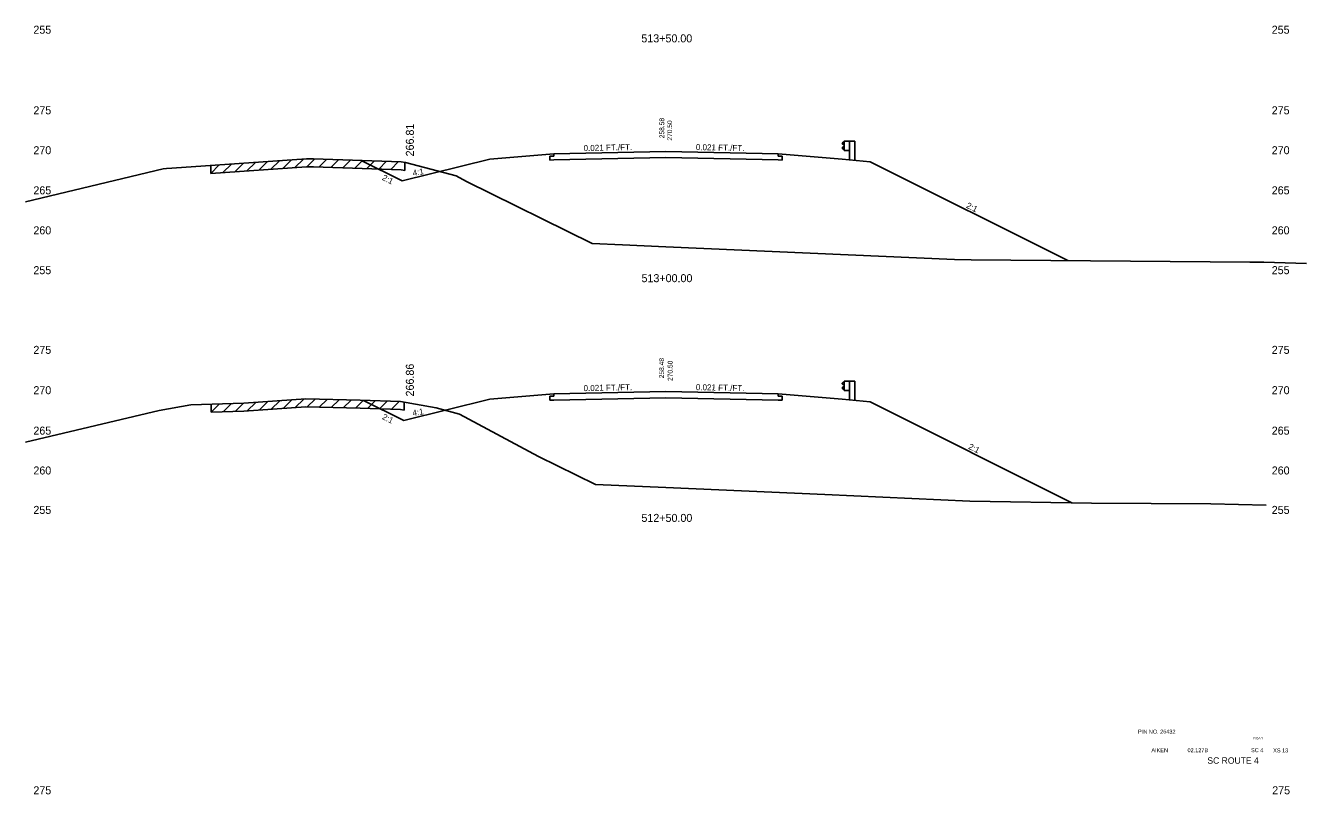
# Model space of a CAD drawing. Extents: x 883 to 1160, y 1002 to 4323.
# Drawn here: x 1000 to 1160, y 2475.1 to 2571.2 of the extents above; entities that cross this region are included whole.
import ezdxf

# ---------------------------------------------------------------- set-up
doc = ezdxf.new("R2010")
doc.units = 0
for name, color, linetype in [('Level 1', 7, 'Continuous'), ('Level 10', 7, 'Continuous'), ('Level 11', 7, 'Continuous'), ('Level 12', 7, 'Continuous'), ('Level 24', 7, 'Continuous'), ('Level 3', 7, 'Continuous'), ('Level 32', 7, 'Continuous'), ('Level 33', 7, 'Continuous'), ('Level 59', 7, 'Continuous'), ('Level 6', 7, 'Continuous'), ('Level 60', 7, 'Continuous'), ('Level 61', 7, 'Continuous'), ('Level 7', 7, 'Continuous')]:
    doc.layers.add(name, color=color, linetype=linetype)

msp = doc.modelspace()

# ---------------------------------------------------------------- linework, layer by layer
at = {"layer": 'Level 11'}
for p, q in [((1066, 2555.21), (1066, 2554.91)), ((1094, 2554.91), (1094, 2555.21)), ((1066, 2554.91), (1065.5, 2554.9)), ((1065.5, 2554.9), (1065.5, 2554.42)), ((1065.5, 2554.42), (1066, 2554.43)), ((1094.5, 2554.9), (1094, 2554.91)), ((1094, 2554.43), (1094.5, 2554.42)), ((1094.5, 2554.42), (1094.5, 2554.9)), ((1066, 2524.91), (1065.5, 2524.9)), ((1065.5, 2524.9), (1065.5, 2524.42)), ((1066, 2525.21), (1066, 2524.91)), ((1094, 2524.91), (1094, 2525.21)), ((1094.5, 2524.9), (1094, 2524.91)), ((1094.5, 2524.42), (1094.5, 2524.9)), ((1065.5, 2524.42), (1066, 2524.43)), ((1094, 2524.43), (1094.5, 2524.42))]:
    msp.add_line(p, q, dxfattribs=at)
at = {"layer": 'Level 12'}
for p, q in [((1080, 2554.72), (1066, 2554.43)), ((1094, 2554.43), (1080, 2554.72)), ((1080, 2524.72), (1066, 2524.43)), ((1094, 2524.43), (1080, 2524.72))]:
    msp.add_line(p, q, dxfattribs=at)
at = {"layer": 'Level 24'}
for p, q in [((1102.27, 2556.72), (1102, 2556.52)), ((1102, 2556.52), (1102, 2556.47)), ((1102, 2556.47), (1102.27, 2556.27)), ((1102, 2555.95), (1102.27, 2556.15)), ((1102, 2555.9), (1102, 2555.95)), ((1102.27, 2555.7), (1102, 2555.9)), ((1102.27, 2555.63), (1102.27, 2556.79)), ((1102.27, 2556.79), (1102.94, 2556.79)), ((1102.27, 2555.63), (1102.94, 2555.63)), ((1102.94, 2556.79), (1102.94, 2554.45)), ((1102.94, 2556.79), (1103.6, 2556.79)), ((1103.6, 2556.79), (1103.6, 2554.38)), ((1102.27, 2526.72), (1102, 2526.52)), ((1102, 2526.52), (1102, 2526.47)), ((1102, 2526.47), (1102.27, 2526.27)), ((1102.27, 2525.63), (1102.27, 2526.79)), ((1102.27, 2526.79), (1102.94, 2526.79)), ((1102.94, 2526.79), (1102.94, 2524.45)), ((1102.94, 2526.79), (1103.6, 2526.79)), ((1103.6, 2526.79), (1103.6, 2524.38)), ((1102, 2525.95), (1102.27, 2526.15)), ((1102, 2525.9), (1102, 2525.95)), ((1102.27, 2525.7), (1102, 2525.9)), ((1102.27, 2525.63), (1102.94, 2525.63))]:
    msp.add_line(p, q, dxfattribs=at)
at = {"layer": 'Level 59'}
for p, q in [((1066, 2555.21), (1080, 2555.5)), ((1080, 2555.5), (1094, 2555.21)), ((1066, 2525.21), (1080, 2525.5)), ((1080, 2525.5), (1094, 2525.21))]:
    msp.add_line(p, q, dxfattribs=at)
at = {"layer": 'Level 6'}
for p, q in [((1058, 2554.54), (1066, 2555.21)), ((1094, 2555.21), (1102, 2554.54)), ((1102, 2554.54), (1105.5, 2554.19)), ((1058, 2524.54), (1066, 2525.21)), ((1094, 2525.21), (1102, 2524.54)), ((1102, 2524.54), (1105.5, 2524.19))]:
    msp.add_line(p, q, dxfattribs=at)
at = {"layer": 'Level 60'}
for p, q in [((1018.28, 2553.4), (1035.1, 2554.58)), ((1035.1, 2554.58), (1035.95, 2554.56)), ((1035.95, 2554.56), (1046.9, 2554.21)), ((1046.9, 2554.21), (1047.47, 2554.11)), ((1047.47, 2554.11), (1053.79, 2552.44)), ((1000, 2549.22), (1017.2, 2553.31)), ((1017.2, 2553.31), (1017.61, 2553.38)), ((1017.61, 2553.38), (1018.28, 2553.4)), ((1053.79, 2552.44), (1055.06, 2551.76)), ((1055.06, 2551.76), (1070.79, 2543.99)), ((1070.79, 2543.99), (1074.55, 2543.83)), ((1074.55, 2543.83), (1080, 2543.58)), ((1080, 2543.58), (1116.04, 2541.98)), ((1116.04, 2541.98), (1118.13, 2541.95)), ((1118.13, 2541.95), (1152.92, 2541.67)), ((1152.92, 2541.67), (1154.67, 2541.64)), ((1154.67, 2541.64), (1160, 2541.49)), ((1016.67, 2523.12), (1020.66, 2523.84)), ((1020.66, 2523.84), (1027.26, 2524.04)), ((1027.26, 2524.04), (1035.02, 2524.58)), ((1035.02, 2524.58), (1041.8, 2524.4)), ((1041.8, 2524.4), (1046.84, 2524.24)), ((1046.84, 2524.24), (1051.3, 2523.44)), ((1051.3, 2523.44), (1054.2, 2522.68)), ((1000, 2519.15), (1016.67, 2523.12)), ((1054.2, 2522.68), (1064.08, 2517.38)), ((1064.08, 2517.38), (1071.19, 2513.87)), ((1071.19, 2513.87), (1080, 2513.48)), ((1080, 2513.48), (1099.85, 2512.61)), ((1099.85, 2512.61), (1117.96, 2511.81)), ((1117.96, 2511.81), (1133.16, 2511.56)), ((1133.16, 2511.56), (1148.05, 2511.44)), ((1148.05, 2511.44), (1154.96, 2511.3))]:
    msp.add_line(p, q, dxfattribs=at)
at = {"layer": 'Level 61'}
for p, q in [((1024.2, 2553.82), (1023.13, 2552.74)), ((1023.13, 2553.74), (1023.13, 2552.74)), ((1025.7, 2553.92), (1024.63, 2552.85)), ((1027.2, 2554.03), (1026.13, 2552.95)), ((1028.7, 2554.13), (1027.63, 2553.06)), ((1030.2, 2554.24), (1029.13, 2553.16)), ((1031.7, 2554.34), (1030.63, 2553.27)), ((1033.2, 2554.45), (1032.13, 2553.37)), ((1034.7, 2554.55), (1033.63, 2553.48)), ((1036.1, 2554.55), (1035.13, 2553.58)), ((1037.6, 2554.51), (1036.63, 2553.54)), ((1039.1, 2554.46), (1038.13, 2553.49)), ((1040.6, 2554.41), (1039.63, 2553.44)), ((1042.1, 2554.36), (1041.13, 2553.39)), ((1043.6, 2554.32), (1042.63, 2553.35)), ((1045.1, 2554.27), (1044.13, 2553.3)), ((1046.6, 2554.22), (1045.63, 2553.25)), ((1047.36, 2553.13), (1047.36, 2554.13)), ((1023.13, 2552.74), (1035.1, 2553.58)), ((1035.1, 2553.58), (1035.95, 2553.56)), ((1035.95, 2553.56), (1046.9, 2553.21)), ((1046.9, 2553.21), (1047.36, 2553.13)), ((1024.22, 2523.95), (1023.19, 2522.91)), ((1023.19, 2523.91), (1023.19, 2522.91)), ((1025.72, 2523.99), (1024.69, 2522.96)), ((1027.22, 2524.04), (1026.19, 2523)), ((1027.26, 2523.04), (1035.02, 2523.58)), ((1028.77, 2524.14), (1027.69, 2523.07)), ((1030.27, 2524.25), (1029.19, 2523.17)), ((1031.77, 2524.35), (1030.69, 2523.28)), ((1033.27, 2524.46), (1032.19, 2523.38)), ((1034.77, 2524.56), (1033.69, 2523.49)), ((1035.02, 2523.58), (1041.8, 2523.4)), ((1036.17, 2524.55), (1035.19, 2523.58)), ((1037.67, 2524.51), (1036.69, 2523.53)), ((1039.17, 2524.47), (1038.19, 2523.49)), ((1040.67, 2524.43), (1039.69, 2523.45)), ((1042.16, 2524.39), (1041.19, 2523.41)), ((1041.8, 2523.4), (1046.84, 2523.24)), ((1043.66, 2524.34), (1042.69, 2523.37)), ((1045.16, 2524.29), (1044.19, 2523.32)), ((1046.66, 2524.24), (1045.69, 2523.27)), ((1046.84, 2523.24), (1047.29, 2523.16)), ((1047.29, 2523.16), (1047.29, 2524.16)), ((1023.19, 2522.91), (1027.26, 2523.04))]:
    msp.add_line(p, q, dxfattribs=at)
at = {"layer": 'Level 7'}
for p, q in [((1041.93, 2554.37), (1047.05, 2551.81)), ((1058, 2554.54), (1047.05, 2551.81)), ((1105.5, 2554.19), (1130.18, 2541.85)), ((1042.2, 2524.38), (1047.25, 2521.86)), ((1058, 2524.54), (1047.25, 2521.86)), ((1105.5, 2524.19), (1130.68, 2511.6))]:
    msp.add_line(p, q, dxfattribs=at)

# ---------------------------------------------------------------- texts
at = {"layer": 'Level 1'}
for s, height, p in [('513+50.00', 1, (1076.92, 2569.13)), ('513+00.00', 1, (1076.94, 2539.16)), ('512+50.00', 1, (1076.93, 2509.2)), ('PIN NO. 26432', 0.5, (1138.97, 2482.74)), ('AIKEN', 0.5, (1140.64, 2480.42)), ('02.127B', 0.5, (1145.15, 2480.42)), ('SC 4', 0.5, (1153.09, 2480.42)), ('XS 13', 0.5, (1155.85, 2480.39)), ('SC ROUTE 4', 0.8, (1147.63, 2478.98))]:
    msp.add_text(s, height=height, dxfattribs=at).set_placement(p)
at = {"layer": 'Level 10'}
for s, p in [('258.58', (1079.78, 2557.15)), ('258.48', (1079.75, 2527.15))]:
    msp.add_text(s, height=0.6, rotation=90, dxfattribs=at).set_placement(p)
at = {"layer": 'Level 3'}
for s, height, p in [(' 255', 1, (1000.6, 2570.21)), (' 255', 1, (1155.3, 2570.21)), (' 275', 1, (1000.6, 2560.14)), (' 275', 1, (1155.3, 2560.14)), (' 270', 1, (1000.6, 2555.15)), (' 270', 1, (1155.3, 2555.15)), (' 265', 1, (1000.6, 2550.14)), (' 265', 1, (1155.3, 2550.14)), (' 260', 1, (1000.6, 2545.14)), (' 260', 1, (1155.3, 2545.14)), (' 255', 1, (1000.6, 2540.16)), (' 255', 1, (1155.3, 2540.16)), (' 275', 1, (1000.6, 2530.2)), (' 275', 1, (1155.3, 2530.2)), (' 270', 1, (1000.6, 2525.16)), (' 270', 1, (1155.3, 2525.16)), (' 265', 1, (1000.6, 2520.11)), (' 265', 1, (1155.3, 2520.11)), (' 260', 1, (1000.6, 2515.13)), (' 260', 1, (1155.3, 2515.13)), (' 255', 1, (1000.6, 2510.2)), (' 255', 1, (1155.3, 2510.2)), ('ROAD', 0.3, (1153.38, 2482.01)), (' 275', 1, (1000.6, 2475.16)), (' 275', 1, (1155.36, 2475.16))]:
    msp.add_text(s, height=height, dxfattribs=at).set_placement(p)
at = {"layer": 'Level 32'}
for s, rotation, p in [('0.021 FT./FT.', 1.1916, (1069.71, 2555.54)), ('0.021 FT./FT.', 358.8084, (1083.72, 2555.67)), ('2:1', 333.435, (1044.46, 2551.98)), ('4:1', 9.4623, (1048.42, 2552.43)), ('2:1', 333.435, (1117.44, 2548.5)), ('0.021 FT./FT.', 1.1916, (1069.71, 2525.54)), ('0.021 FT./FT.', 358.8084, (1083.72, 2525.67)), ('4:1', 9.4623, (1048.39, 2522.43)), ('2:1', 333.435, (1044.47, 2522.08)), ('2:1', 333.435, (1117.7, 2518.37))]:
    msp.add_text(s, height=0.75, rotation=rotation, dxfattribs=at).set_placement(p)
at = {"layer": 'Level 33'}
for s, p in [('266.81', (1048.5, 2554.88)), ('266.86', (1048.5, 2524.88))]:
    msp.add_text(s, height=1, rotation=90, dxfattribs=at).set_placement(p)
at = {"layer": 'Level 59'}
for p in [(1080.76, 2556.62), (1080.82, 2526.59)]:
    msp.add_text(' 270.50', height=0.6, rotation=90, dxfattribs=at).set_placement(p)

doc.saveas('drawing.dxf')
